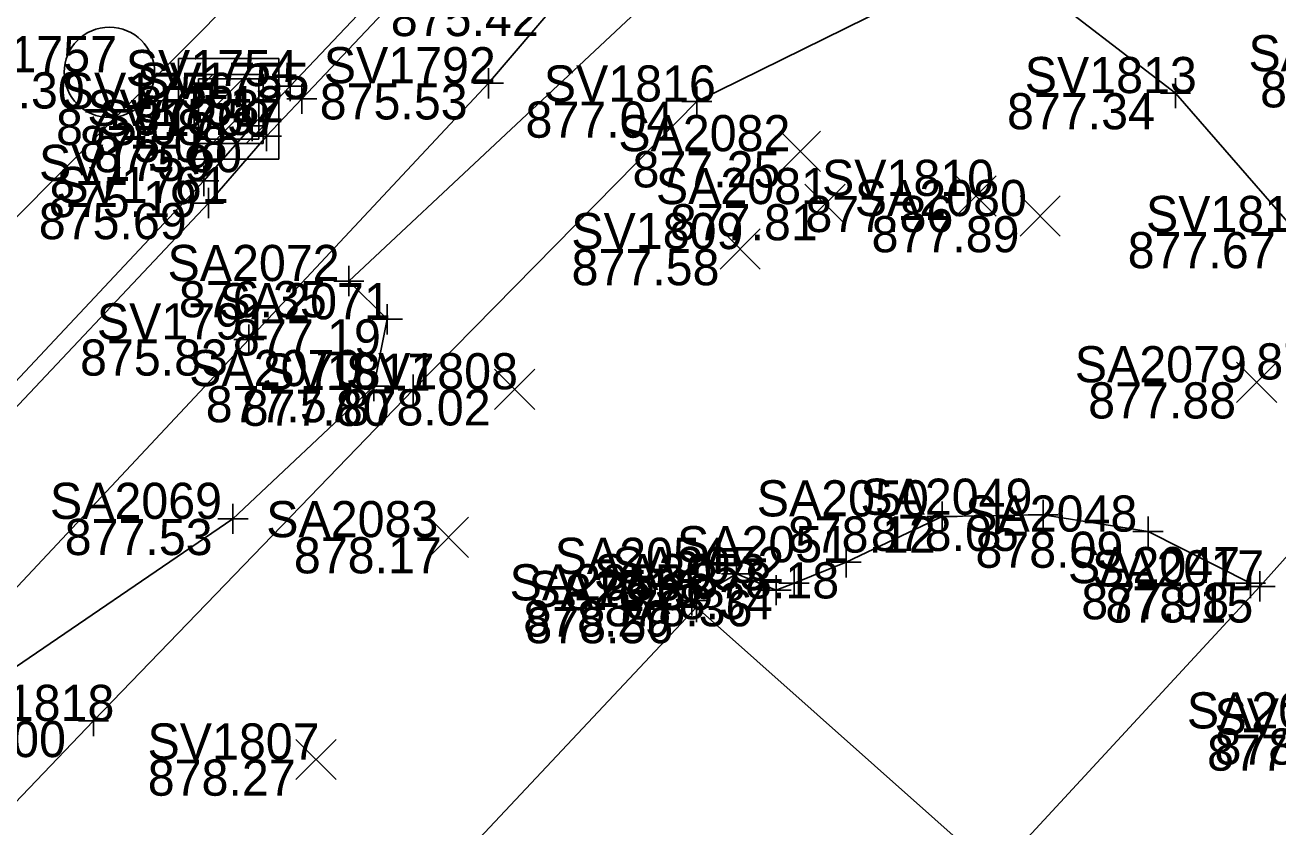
# Model space of a CAD drawing. Extents: x 1480001 to 1480402, y 379235 to 379603.
# Drawn here: x 1480138.03 to 1480179.61, y 379347.34 to 379373.95 of the extents above; entities that cross this region are included whole.
import ezdxf

# ---------------------------------------------------------------- set-up
doc = ezdxf.new("R2010")
doc.units = 0
for name, color, linetype in [('DR_X_Cells', 7, 'Continuous'), ('GE_X_Cells', 7, 'Continuous'), ('GK_Drainage_Nodes', 7, 'Continuous'), ('PV_X_Curb', 7, 'Continuous'), ('PV_X_Walk', 7, 'Continuous'), ('SV_X_Break_Lines', 7, 'Continuous'), ('SV_X_Random_Point', 7, 'Continuous'), ('SV_X_Shot_Marker', 7, 'Continuous'), ('SV_X_Text_Elevation', 7, 'Continuous'), ('SV_X_Text_Name', 7, 'Continuous'), ('UT_X_Water', 7, 'Continuous'), ('VG_X_Flower_Bed', 7, 'Continuous')]:
    doc.layers.add(name, color=color, linetype=linetype)

msp = doc.modelspace()

# ---------------------------------------------------------------- linework, layer by layer
at = {"layer": 'DR_X_Cells'}
for p, q in [((1480143.64, 379370.559), (1480145.399, 379372.318)), ((1480143.64, 379371.691), (1480144.268, 379372.318)), ((1480144.239, 379370.027), (1480145.932, 379371.72)), ((1480145.37, 379370.027), (1480145.932, 379370.588))]:
    msp.add_line(p, q, dxfattribs=at)
for points in [[(1480143.119, 379372.839), (1480146.453, 379372.839), (1480146.453, 379369.506), (1480143.119, 379369.506)], [(1480143.64, 379372.318), (1480145.932, 379372.318), (1480145.932, 379370.027), (1480143.64, 379370.027)], [(1480143.786, 379372.172), (1480145.786, 379372.172), (1480145.786, 379370.172), (1480143.786, 379370.172)]]:
    msp.add_lwpolyline(points, close=True, dxfattribs=at)
at = {"layer": 'GE_X_Cells'}
msp.add_circle((1480140.831, 379372.385), 1.5, dxfattribs=at)
at = {"layer": 'GK_Drainage_Nodes'}
for p, q in [((1480144.786, 379372.839), (1480144.786, 379372.839)), ((1480144.786, 379372.172), (1480144.786, 379372.172)), ((1480143.786, 379371.172), (1480143.786, 379371.172)), ((1480144.786, 379371.172), (1480144.786, 379371.172)), ((1480144.786, 379371.172), (1480144.786, 379371.172)), ((1480144.786, 379371.172), (1480144.786, 379371.172)), ((1480145.786, 379371.172), (1480145.786, 379371.172)), ((1480144.786, 379370.172), (1480144.786, 379370.172)), ((1480144.786, 379369.506), (1480144.786, 379369.506))]:
    msp.add_line(p, q, dxfattribs=at)
at = {"layer": 'PV_X_Curb'}
for points in [[(1480155.238, 379379.795), (1480153.548, 379379.014), (1480146.824, 379371.927), (1480145.567, 379370.605), (1480143.964, 379368.78), (1480128.12, 379351.892), (1480112.56, 379335.214), (1480098.785, 379320.255), (1480094.793, 379316.092), (1480093.124, 379314.172), (1480085.166, 379305.624), (1480081.585, 379301.702), (1480079.854, 379299.882), (1480067.172, 379286.11), (1480056.531, 379274.485), (1480055.169, 379272.969)], [(1480155.431, 379379.884), (1480153.98, 379378.667), (1480147.216, 379371.505), (1480146.047, 379370.27), (1480144.119, 379368.047), (1480128.647, 379351.629), (1480112.741, 379334.357), (1480099.146, 379319.858), (1480095.569, 379316.008), (1480093.53, 379313.846), (1480085.356, 379305.01), (1480081.967, 379301.397), (1480080.218, 379299.413), (1480067.589, 379285.613), (1480056.688, 379273.774), (1480055.547, 379272.623)]]:
    msp.add_lwpolyline(points, dxfattribs=at)
at = {"layer": 'PV_X_Walk'}
for points in [[(1480059.793, 379271.54), (1480075.261, 379288.048), (1480088.444, 379302.419), (1480096.088, 379310.695), (1480098.33, 379313.163), (1480111.975, 379327.613), (1480128.977, 379345.933), (1480145.46, 379363.52), (1480153.413, 379372.021), (1480155.772, 379374.786), (1480158.213, 379377.107), (1480160.137, 379378.801), (1480161.631, 379379.994)], [(1480108.223, 379298.793), (1480126.311, 379318.205), (1480145.385, 379338.742), (1480160.312, 379354.639), (1480170.225, 379345.82), (1480179.011, 379355.326), (1480188.24, 379365.647)]]:
    msp.add_lwpolyline(points, dxfattribs=at)
at = {"layer": 'SV_X_Break_Lines'}
for points in [[(1480109.136, 379300.654), (1480103.503, 379307.396), (1480120.541, 379324.578), (1480124.787, 379337.805), (1480137.007, 379352.173), (1480144.932, 379357.565), (1480149.611, 379361.971), (1480150.052, 379364.189), (1480148.777, 379365.458), (1480163.875, 379379.601), (1480168.818, 379380.654), (1480172.802, 379381.332), (1480178.472, 379378.317), (1480184.655, 379372.421), (1480187.645, 379366.317)], [(1480184.481, 379363.392), (1480180.224, 379367.084), (1480176.21, 379371.695), (1480171.222, 379375.535), (1480168.077, 379375.239), (1480160.326, 379371.415), (1480150.91, 379361.854), (1480140.301, 379350.86), (1480130.798, 379340.93), (1480121.664, 379330.001), (1480112.679, 379319.616)]]:
    msp.add_lwpolyline(points, dxfattribs=at)
at = {"layer": 'SV_X_Random_Point'}
for p, q in [((1480163.088, 379369.099), (1480164.422, 379370.434)), ((1480163.088, 379370.434), (1480164.422, 379369.099)), ((1480168.92, 379367.617), (1480170.254, 379368.952)), ((1480168.92, 379368.952), (1480170.254, 379367.617)), ((1480163.911, 379367.344), (1480165.245, 379368.679)), ((1480163.911, 379368.679), (1480165.245, 379367.344)), ((1480171.049, 379366.947), (1480172.382, 379368.282)), ((1480171.049, 379368.282), (1480172.382, 379366.947)), ((1480161.093, 379365.852), (1480162.427, 379367.187)), ((1480161.093, 379367.187), (1480162.427, 379365.852)), ((1480178.236, 379361.431), (1480179.569, 379362.766)), ((1480178.236, 379362.766), (1480179.569, 379361.431)), ((1480153.613, 379361.199), (1480154.947, 379362.534)), ((1480153.613, 379362.534), (1480154.947, 379361.199)), ((1480151.415, 379356.29), (1480152.749, 379357.625)), ((1480151.415, 379357.625), (1480152.749, 379356.29)), ((1480147.021, 379348.913), (1480148.355, 379350.248)), ((1480147.021, 379350.248), (1480148.355, 379348.913))]:
    msp.add_line(p, q, dxfattribs=at)
at = {"layer": 'SV_X_Shot_Marker'}
for p, q in [((1480146.824, 379372.427), (1480146.824, 379371.427)), ((1480153.413, 379372.521), (1480153.413, 379371.521)), ((1480146.324, 379371.927), (1480147.324, 379371.927)), ((1480146.824, 379371.927), (1480146.824, 379371.927)), ((1480147.216, 379372.005), (1480147.216, 379371.005)), ((1480152.913, 379372.021), (1480153.913, 379372.021)), ((1480153.413, 379372.021), (1480153.413, 379372.021)), ((1480160.326, 379371.915), (1480160.326, 379370.915)), ((1480176.21, 379372.195), (1480176.21, 379371.195)), ((1480146.716, 379371.505), (1480147.716, 379371.505)), ((1480147.216, 379371.505), (1480147.216, 379371.505)), ((1480159.826, 379371.415), (1480160.826, 379371.415)), ((1480160.326, 379371.415), (1480160.326, 379371.415)), ((1480175.71, 379371.695), (1480176.71, 379371.695)), ((1480176.21, 379371.695), (1480176.21, 379371.695)), ((1480145.567, 379371.105), (1480145.567, 379370.105)), ((1480145.067, 379370.605), (1480146.067, 379370.605)), ((1480145.567, 379370.605), (1480145.567, 379370.605)), ((1480146.047, 379370.77), (1480146.047, 379369.77)), ((1480145.547, 379370.27), (1480146.547, 379370.27)), ((1480146.047, 379370.27), (1480146.047, 379370.27)), ((1480143.964, 379369.28), (1480143.964, 379368.28)), ((1480143.464, 379368.78), (1480144.464, 379368.78)), ((1480143.964, 379368.78), (1480143.964, 379368.78)), ((1480144.119, 379368.547), (1480144.119, 379367.547)), ((1480143.619, 379368.047), (1480144.619, 379368.047)), ((1480144.119, 379368.047), (1480144.119, 379368.047)), ((1480148.777, 379365.958), (1480148.777, 379364.958)), ((1480148.277, 379365.458), (1480149.277, 379365.458)), ((1480148.777, 379365.458), (1480148.777, 379365.458)), ((1480150.052, 379364.689), (1480150.052, 379363.689)), ((1480145.46, 379364.02), (1480145.46, 379363.02)), ((1480149.552, 379364.189), (1480150.552, 379364.189)), ((1480150.052, 379364.189), (1480150.052, 379364.189)), ((1480144.96, 379363.52), (1480145.96, 379363.52)), ((1480145.46, 379363.52), (1480145.46, 379363.52)), ((1480149.611, 379362.471), (1480149.611, 379361.471)), ((1480150.91, 379362.354), (1480150.91, 379361.354)), ((1480149.111, 379361.971), (1480150.111, 379361.971)), ((1480149.611, 379361.971), (1480149.611, 379361.971)), ((1480150.41, 379361.854), (1480151.41, 379361.854)), ((1480150.91, 379361.854), (1480150.91, 379361.854)), ((1480168.462, 379358.148), (1480168.462, 379357.148)), ((1480171.816, 379358.202), (1480171.816, 379357.202)), ((1480144.932, 379358.065), (1480144.932, 379357.065)), ((1480171.316, 379357.702), (1480172.316, 379357.702)), ((1480171.816, 379357.702), (1480171.816, 379357.702)), ((1480144.432, 379357.565), (1480145.432, 379357.565)), ((1480144.932, 379357.565), (1480144.932, 379357.565)), ((1480167.962, 379357.648), (1480168.962, 379357.648)), ((1480168.462, 379357.648), (1480168.462, 379357.648)), ((1480175.295, 379357.643), (1480175.295, 379356.643)), ((1480174.795, 379357.143), (1480175.795, 379357.143)), ((1480175.295, 379357.143), (1480175.295, 379357.143)), ((1480165.279, 379356.626), (1480165.279, 379355.626)), ((1480161.643, 379356.241), (1480161.643, 379355.241)), ((1480164.779, 379356.126), (1480165.779, 379356.126)), ((1480165.279, 379356.126), (1480165.279, 379356.126)), ((1480161.143, 379355.741), (1480162.143, 379355.741)), ((1480161.643, 379355.741), (1480161.643, 379355.741)), ((1480162.959, 379355.701), (1480162.959, 379354.701)), ((1480163.55, 379355.938), (1480163.55, 379354.938)), ((1480178.694, 379355.933), (1480178.694, 379354.933)), ((1480179.011, 379355.826), (1480179.011, 379354.826)), ((1480160.157, 379355.361), (1480160.157, 379354.361)), ((1480162.459, 379355.201), (1480163.459, 379355.201)), ((1480162.959, 379355.201), (1480162.959, 379355.201)), ((1480163.05, 379355.438), (1480164.05, 379355.438)), ((1480163.55, 379355.438), (1480163.55, 379355.438)), ((1480178.194, 379355.433), (1480179.194, 379355.433)), ((1480178.511, 379355.326), (1480179.511, 379355.326)), ((1480178.694, 379355.433), (1480178.694, 379355.433)), ((1480179.011, 379355.326), (1480179.011, 379355.326)), ((1480159.657, 379354.861), (1480160.657, 379354.861)), ((1480160.157, 379354.861), (1480160.157, 379354.861)), ((1480160.312, 379355.139), (1480160.312, 379354.139)), ((1480159.812, 379354.639), (1480160.812, 379354.639)), ((1480160.312, 379354.639), (1480160.312, 379354.639)), ((1480140.301, 379351.36), (1480140.301, 379350.36)), ((1480139.801, 379350.86), (1480140.801, 379350.86)), ((1480140.301, 379350.86), (1480140.301, 379350.86))]:
    msp.add_line(p, q, dxfattribs=at)
at = {"layer": 'UT_X_Water'}
msp.add_lwpolyline([(1480169.204, 379397.823), (1480165.761, 379394.087), (1480162.59, 379391.88), (1480159.156, 379388.706), (1480148.911, 379378.819), (1480120.344, 379350.087), (1480106.297, 379335.736), (1480080.736, 379308.289), (1480073.091, 379299.637), (1480056.748, 379281.628), (1480051.266, 379275.974)], dxfattribs=at)
at = {"layer": 'VG_X_Flower_Bed'}
msp.add_lwpolyline([(1480178.694, 379355.433), (1480175.295, 379357.143), (1480171.816, 379357.702), (1480168.462, 379357.648), (1480165.279, 379356.126), (1480163.55, 379355.438), (1480162.959, 379355.201), (1480161.643, 379355.741), (1480160.157, 379354.861)], dxfattribs=at)

# ---------------------------------------------------------------- texts
at = {"layer": 'SV_X_Text_Elevation'}
for s, p in [('875.42', (1480150.169, 379373.586)), ('875.30', (1480135.105, 379371.185)), ('876.48', (1480179.015, 379371.221)), ('875.12', (1480141.704, 379370.727)), ('875.53', (1480147.81, 379370.821)), ('875.57', (1480141.613, 379370.305)), ('877.04', (1480154.638, 379370.215)), ('877.34', (1480170.617, 379370.495)), ('875.08', (1480139.06, 379369.972)), ('875.08', (1480139.841, 379369.405)), ('875.60', (1480140.321, 379369.07)), ('877.25', (1480158.19, 379368.566)), ('875.19', (1480138.825, 379367.58)), ('875.69', (1480138.488, 379366.847)), ('877.86', (1480163.928, 379367.084)), ('877.81', (1480159.428, 379366.811)), ('877.89', (1480166.122, 379366.414)), ('877.67', (1480174.621, 379365.884)), ('877.58', (1480156.167, 379365.319)), ('876.35', (1480143.137, 379364.258)), ('877.19', (1480144.931, 379362.989)), ('875.83', (1480139.857, 379362.32)), ('877.64', (1480178.888, 379362.192)), ('877.57', (1480144.027, 379360.771)), ('877.80', (1480145.222, 379360.654)), ('878.02', (1480148.573, 379360.666)), ('877.88', (1480173.309, 379360.898)), ('878.12', (1480163.342, 379356.448)), ('878.05', (1480166.1, 379356.502)), ('877.53', (1480139.348, 379356.365)), ('878.17', (1480146.952, 379355.758)), ('878.09', (1480169.569, 379355.943)), ('878.18', (1480160.14, 379354.926)), ('878.36', (1480155.946, 379354.541)), ('878.36', (1480157.262, 379354.001)), ('878.34', (1480157.938, 379354.238)), ('877.98', (1480173.082, 379354.233)), ('878.15', (1480173.881, 379354.126)), ('878.29', (1480154.564, 379353.661)), ('878.56', (1480154.634, 379353.439)), ('878.00', (1480134.481, 379349.66)), ('878.18', (1480177.502, 379349.412)), ('877.96', (1480177.255, 379349.211)), ('878.27', (1480142.104, 379348.38))]:
    msp.add_text(s, height=1.2, dxfattribs=at).set_placement(p)
at = {"layer": 'SV_X_Text_Name'}
for s, p in [('SV1757', (1480135.371, 379372.385)), ('SA2077', (1480178.628, 379372.421)), ('SV1754', (1480141.373, 379371.927)), ('SV1792', (1480147.943, 379372.021)), ('SV1755', (1480141.756, 379371.505)), ('SV1816', (1480155.244, 379371.415)), ('SV1813', (1480171.204, 379371.695)), ('SV1756', (1480139.25, 379371.172)), ('SV1758', (1480140.097, 379370.605)), ('SV1760', (1480140.464, 379370.27)), ('SA2082', (1480157.718, 379369.766)), ('SV1759', (1480138.494, 379368.78)), ('SV1810', (1480164.477, 379368.284)), ('SV1761', (1480139.074, 379368.047)), ('SA2081', (1480158.965, 379368.011)), ('SA2080', (1480165.565, 379367.614)), ('SV1812', (1480175.227, 379367.084)), ('SV1809', (1480156.158, 379366.519)), ('SA2072', (1480142.759, 379365.458)), ('SA2071', (1480144.458, 379364.189)), ('SV1791', (1480140.415, 379363.52)), ('SA2070', (1480143.479, 379361.971)), ('SV1817', (1480145.904, 379361.854)), ('SV1808', (1480148.678, 379361.866)), ('SA2079', (1480172.865, 379362.098)), ('SA2049', (1480165.75, 379357.702)), ('SA2069', (1480138.857, 379357.565)), ('SA2050', (1480162.311, 379357.648)), ('SA2083', (1480146.035, 379356.958)), ('SA2048', (1480169.229, 379357.143)), ('SA2051', (1480159.666, 379356.126)), ('SA2054', (1480155.606, 379355.741)), ('SA2053', (1480156.912, 379355.201)), ('SA2052', (1480157.513, 379355.438)), ('SA2047', (1480172.638, 379355.433)), ('SA2017', (1480173.437, 379355.326)), ('SA2055', (1480154.11, 379354.861)), ('SA2015', (1480154.739, 379354.639)), ('SV1818', (1480135.285, 379350.86)), ('SA2045', (1480176.585, 379350.612)), ('SV1722', (1480177.501, 379350.411)), ('SV1807', (1480142.095, 379349.58))]:
    msp.add_text(s, height=1.2, dxfattribs=at).set_placement(p)

doc.saveas('drawing.dxf')
